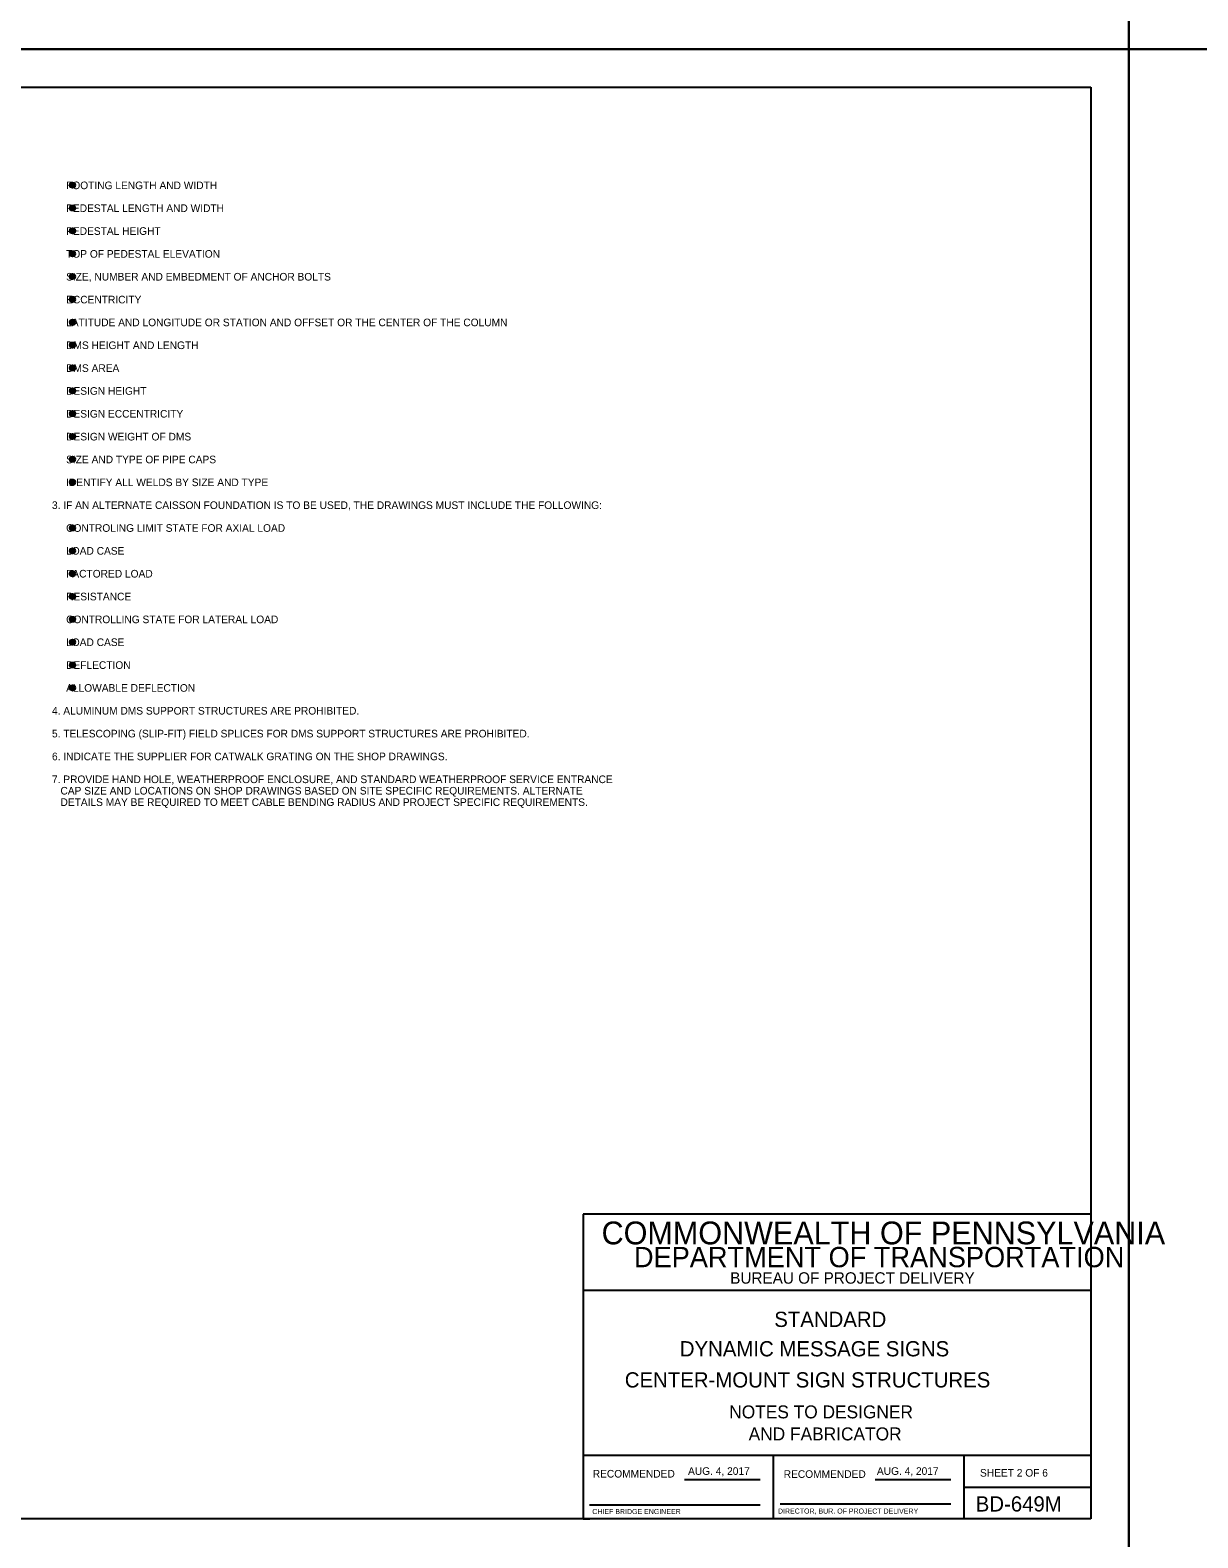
# Model space of a CAD drawing. Extents: x 3829340 to 3831660, y 499389 to 501171.
# Drawn here: x 3829748 to 3830208, y 499991 to 500585 of the extents above; entities that cross this region are included whole.
import ezdxf

# ---------------------------------------------------------------- set-up
doc = ezdxf.new("R2010")
doc.units = 0
for name, color, linetype in [('10', 7, 'Continuous'), ('2', 7, 'Continuous'), ('DIM TXT', 7, 'Continuous'), ('PLT-BNDY', 7, 'Continuous'), ('Pr_dimension_ln', 7, 'Continuous')]:
    doc.layers.add(name, color=color, linetype=linetype)

msp = doc.modelspace()

# ---------------------------------------------------------------- linework, layer by layer
at = {"layer": '2'}
for p, q in [((3829379.96, 500562.19), (3830165.96, 500562.19)), ((3830165.96, 500562.19), (3830165.96, 499998.19)), ((3830165.96, 500118.19), (3829965.96, 500118.19)), ((3829965.96, 500118.19), (3829965.96, 499998.19)), ((3830165.96, 500088.19), (3829965.96, 500088.19)), ((3830165.96, 500023.19), (3829965.96, 500023.19)), ((3830040.96, 499998.19), (3830040.96, 500023.19)), ((3830115.96, 500023.19), (3830115.96, 499998.19)), ((3830005.93, 500013.69), (3830035.69, 500013.69)), ((3830080.93, 500013.69), (3830110.83, 500013.69)), ((3830115.96, 500010.69), (3830165.96, 500010.69)), ((3829968.46, 500003.69), (3830035.69, 500003.69)), ((3830043.59, 500004.06), (3830110.83, 500004.06)), ((3830165.96, 499998.19), (3829379.96, 499998.19)), ((3829965.96, 499998.19), (3829968.53, 499998.19))]:
    msp.add_line(p, q, dxfattribs=at)
at = {"layer": 'DIM TXT'}
for centre, radius in [((3829764.81, 500523.61), 1.04), ((3829764.81, 500523.61), 0.783), ((3829764.81, 500523.61), 0.522), ((3829764.81, 500523.61), 0.261), ((3829764.81, 500523.61), 0.00000209), ((3829764.81, 500514.61), 1.04), ((3829764.81, 500514.61), 0.783), ((3829764.81, 500514.61), 0.522), ((3829764.81, 500514.61), 0.261), ((3829764.81, 500514.61), 0.00000209), ((3829764.81, 500505.61), 1.04), ((3829764.81, 500505.61), 0.783), ((3829764.81, 500505.61), 0.522), ((3829764.81, 500505.61), 0.261), ((3829764.81, 500505.61), 0.00000209), ((3829764.81, 500496.61), 1.04), ((3829764.81, 500496.61), 0.783), ((3829764.81, 500496.61), 0.522), ((3829764.81, 500496.61), 0.261), ((3829764.81, 500496.61), 0.00000209), ((3829764.81, 500487.61), 1.04), ((3829764.81, 500487.61), 0.783), ((3829764.81, 500487.61), 0.522), ((3829764.81, 500487.61), 0.261), ((3829764.81, 500487.61), 0.00000209), ((3829764.81, 500478.61), 1.04), ((3829764.81, 500478.61), 0.783), ((3829764.81, 500478.61), 0.522), ((3829764.81, 500478.61), 0.261), ((3829764.81, 500478.61), 0.00000209), ((3829764.81, 500469.61), 1.04), ((3829764.81, 500469.61), 0.783), ((3829764.81, 500469.61), 0.522), ((3829764.81, 500469.61), 0.261), ((3829764.81, 500469.61), 0.00000209), ((3829764.81, 500460.61), 1.04), ((3829764.81, 500460.61), 0.783), ((3829764.81, 500460.61), 0.522), ((3829764.81, 500460.61), 0.261), ((3829764.81, 500460.61), 0.00000209), ((3829764.81, 500451.61), 1.04), ((3829764.81, 500451.61), 0.783), ((3829764.81, 500451.61), 0.522), ((3829764.81, 500451.61), 0.261), ((3829764.81, 500451.61), 0.00000209), ((3829764.81, 500442.61), 1.04), ((3829764.81, 500442.61), 0.783), ((3829764.81, 500442.61), 0.522), ((3829764.81, 500442.61), 0.261), ((3829764.81, 500442.61), 0.00000209), ((3829764.81, 500433.61), 1.04), ((3829764.81, 500433.61), 0.783), ((3829764.81, 500433.61), 0.522), ((3829764.81, 500433.61), 0.261), ((3829764.81, 500433.61), 0.00000209), ((3829764.81, 500424.61), 1.04), ((3829764.81, 500424.61), 0.783), ((3829764.81, 500424.61), 0.522), ((3829764.81, 500424.61), 0.261), ((3829764.81, 500424.61), 0.00000209), ((3829764.81, 500415.61), 1.04), ((3829764.81, 500415.61), 0.783), ((3829764.81, 500415.61), 0.522), ((3829764.81, 500415.61), 0.261), ((3829764.81, 500415.61), 0.00000209), ((3829764.81, 500406.61), 1.04), ((3829764.81, 500406.61), 0.783), ((3829764.81, 500406.61), 0.522), ((3829764.81, 500406.61), 0.261), ((3829764.81, 500406.61), 0.00000209), ((3829764.81, 500388.57), 1.04), ((3829764.81, 500388.57), 0.783), ((3829764.81, 500388.57), 0.522), ((3829764.81, 500388.57), 0.261), ((3829764.81, 500388.57), 0.00000209), ((3829764.81, 500379.57), 1.04), ((3829764.81, 500379.57), 0.783), ((3829764.81, 500379.57), 0.522), ((3829764.81, 500379.57), 0.261), ((3829764.81, 500379.57), 0.00000209), ((3829764.81, 500370.57), 1.04), ((3829764.81, 500370.57), 0.783), ((3829764.81, 500370.57), 0.522), ((3829764.81, 500370.57), 0.261), ((3829764.81, 500370.57), 0.00000209), ((3829764.81, 500361.57), 1.04), ((3829764.81, 500361.57), 0.783), ((3829764.81, 500361.57), 0.522), ((3829764.81, 500361.57), 0.261), ((3829764.81, 500361.57), 0.00000209), ((3829764.81, 500352.57), 1.04), ((3829764.81, 500352.57), 0.783), ((3829764.81, 500352.57), 0.522), ((3829764.81, 500352.57), 0.261), ((3829764.81, 500352.57), 0.00000209), ((3829764.81, 500343.57), 1.04), ((3829764.81, 500343.57), 0.783), ((3829764.81, 500343.57), 0.522), ((3829764.81, 500343.57), 0.261), ((3829764.81, 500343.57), 0.00000209), ((3829764.81, 500334.57), 1.04), ((3829764.81, 500334.57), 0.783), ((3829764.81, 500334.57), 0.522), ((3829764.81, 500334.57), 0.261), ((3829764.81, 500334.57), 0.00000209), ((3829764.81, 500325.57), 1.04), ((3829764.81, 500325.57), 0.783), ((3829764.81, 500325.57), 0.522), ((3829764.81, 500325.57), 0.261), ((3829764.81, 500325.57), 0.00000209)]:
    msp.add_circle(centre, radius, dxfattribs=at)
at = {"layer": 'PLT-BNDY'}
for points in [[(3829339.96, 501171.19), (3830180.96, 501171.19), (3830180.96, 500577.19), (3829339.96, 500577.19)], [(3830180.96, 501171.19), (3831021.96, 501171.19), (3831021.96, 500577.19), (3830180.96, 500577.19)], [(3829339.96, 500577.19), (3830180.96, 500577.19), (3830180.96, 499983.19), (3829339.96, 499983.19)], [(3830180.96, 500577.19), (3831021.96, 500577.19), (3831021.96, 499983.19), (3830180.96, 499983.19)]]:
    msp.add_lwpolyline(points, close=True, dxfattribs=at)

# ---------------------------------------------------------------- texts
at = {"layer": '10'}
for s, height, p in [('STANDARD ', 6, (3830041.23, 500073.77)), ('DYNAMIC MESSAGE SIGNS', 6, (3830004.03, 500062.18)), ('CENTER-MOUNT SIGN STRUCTURES', 6, (3829982.36, 500049.92)), ('NOTES TO DESIGNER', 5.1, (3830023.49, 500037.76)), ('AND FABRICATOR', 5.1, (3830031.14, 500029.09))]:
    msp.add_text(s, height=height, dxfattribs=at).set_placement(p)
at = {"layer": '2'}
for s, height, p in [('COMMONWEALTH OF PENNSYLVANIA', 9, (3829973.21, 500106.31)), ('DEPARTMENT OF TRANSPORTATION', 8.0002, (3829985.96, 500097.31)), ('BUREAU OF PROJECT DELIVERY', 4.5, (3830023.88, 500090.82)), ('RECOMMENDED', 3, (3829969.73, 500014.44)), ('RECOMMENDED', 3, (3830044.95, 500014.31))]:
    msp.add_text(s, height=height, rotation=360, dxfattribs=at).set_placement(p)
for s, height, p in [('AUG. 4, 2017', 3, (3830007.27, 500015.5)), ('AUG. 4, 2017', 3, (3830081.66, 500015.5)), ('SHEET 2 OF 6', 3, (3830122.27, 500014.81)), ('BD-649M', 6, (3830120.59, 500001.06)), ('CHIEF BRIDGE ENGINEER', 2.0002, (3829969.55, 500000.06)), ('  DIRECTOR, BUR. OF PROJECT DELIVERY', 2.0002, (3830041.15, 500000.24))]:
    msp.add_text(s, height=height, dxfattribs=at).set_placement(p)
at = {"layer": 'Pr_dimension_ln'}
for s, p in [('      FOOTING LENGTH AND WIDTH', (3829755.6, 500522.04)), ('      PEDESTAL LENGTH AND WIDTH', (3829755.6, 500513.04)), ('      PEDESTAL HEIGHT', (3829755.6, 500504.04)), ('      TOP OF PEDESTAL ELEVATION', (3829755.6, 500495.04)), ('      SIZE, NUMBER AND EMBEDMENT OF ANCHOR BOLTS', (3829755.6, 500486.04)), ('      ECCENTRICITY', (3829755.6, 500477.04)), ('      LATITUDE AND LONGITUDE OR STATION AND OFFSET OR THE CENTER OF THE COLUMN', (3829755.6, 500468.04)), ('      DMS HEIGHT AND LENGTH', (3829755.6, 500459.04)), ('      DMS AREA', (3829755.6, 500450.04)), ('      DESIGN HEIGHT', (3829755.6, 500441.04)), ('      DESIGN ECCENTRICITY', (3829755.6, 500432.04)), ('      DESIGN WEIGHT OF DMS', (3829755.6, 500423.04)), ('      SIZE AND TYPE OF PIPE CAPS', (3829755.6, 500414.04)), ('      IDENTIFY ALL WELDS BY SIZE AND TYPE ', (3829755.6, 500405.04)), (' 3. IF AN ALTERNATE CAISSON FOUNDATION IS TO BE USED, THE DRAWINGS MUST INCLUDE THE FOLLOWING:', (3829755.6, 500396.04)), ('      CONTROLING LIMIT STATE FOR AXIAL LOAD', (3829755.6, 500387.04)), ('      LOAD CASE', (3829755.6, 500378.04)), ('      FACTORED LOAD', (3829755.6, 500369.04)), ('      RESISTANCE', (3829755.6, 500360.04)), ('      CONTROLLING STATE FOR LATERAL LOAD', (3829755.6, 500351.04)), ('      LOAD CASE', (3829755.6, 500342.04)), ('      DEFLECTION', (3829755.6, 500333.04)), ('      ALLOWABLE DEFLECTION', (3829755.6, 500324.04)), (' 4. ALUMINUM DMS SUPPORT STRUCTURES ARE PROHIBITED.', (3829755.6, 500315.04)), (' 5. TELESCOPING (SLIP-FIT) FIELD SPLICES FOR DMS SUPPORT STRUCTURES ARE PROHIBITED.', (3829755.6, 500306.04)), (' 6. INDICATE THE SUPPLIER FOR CATWALK GRATING ON THE SHOP DRAWINGS.', (3829755.6, 500297.04)), (' 7. PROVIDE HAND HOLE, WEATHERPROOF ENCLOSURE, AND STANDARD WEATHERPROOF SERVICE ENTRANCE ', (3829755.6, 500288.04)), ('    CAP SIZE AND LOCATIONS ON SHOP DRAWINGS BASED ON SITE SPECIFIC REQUIREMENTS. ALTERNATE', (3829755.6, 500283.54)), ('    DETAILS MAY BE REQUIRED TO MEET CABLE BENDING RADIUS AND PROJECT SPECIFIC REQUIREMENTS.', (3829755.6, 500279.04))]:
    msp.add_text(s, height=2.9999, rotation=360, dxfattribs=at).set_placement(p)

doc.saveas('drawing.dxf')
